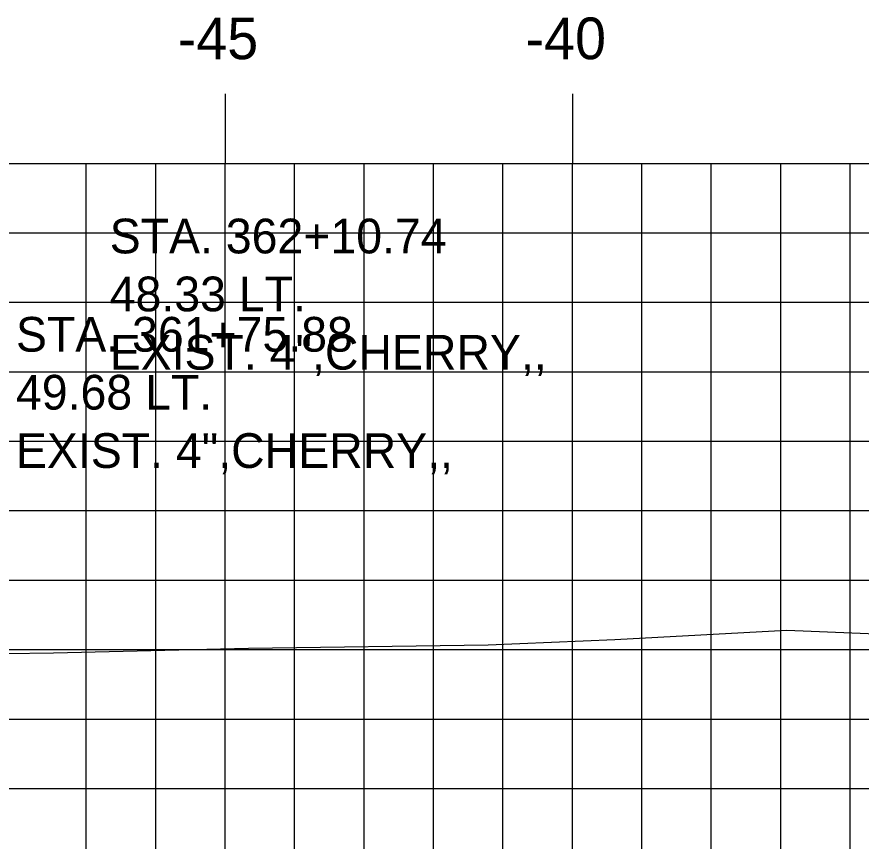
# Model space of a CAD drawing. Extents: x 1146746 to 1146916, y 608981 to 609091.
# Drawn here: x 1146781.43 to 1146793.59, y 609030.58 to 609042.44 of the extents above; entities that cross this region are included whole.
import ezdxf

# ---------------------------------------------------------------- set-up
doc = ezdxf.new("R2010")
doc.units = 0
for name, color, linetype in [('D_Text_Monospaced', 7, 'Continuous'), ('H_V ANNOTATION', 7, 'Continuous'), ('MAJOR', 7, 'Continuous'), ('MINOR', 7, 'Continuous'), ('S_Roadway_Centerline', 7, 'Continuous')]:
    doc.layers.add(name, color=color, linetype=linetype)

msp = doc.modelspace()

# ---------------------------------------------------------------- linework, layer by layer
at = {"layer": 'MAJOR'}
for p, q in [((1146784.428, 609041.337), (1146784.428, 609040.335)), ((1146789.428, 609041.337), (1146789.428, 609040.335)), ((1146759.428, 609040.335), (1146899.428, 609040.335)), ((1146759.428, 609040.335), (1146899.428, 609040.335)), ((1146784.428, 609020.335), (1146784.428, 609040.335)), ((1146789.428, 609020.335), (1146789.428, 609040.335)), ((1146759.428, 609035.335), (1146899.428, 609035.335))]:
    msp.add_line(p, q, dxfattribs=at)
at = {"layer": 'MINOR'}
for p, q in [((1146782.428, 609020.335), (1146782.428, 609040.335)), ((1146783.428, 609020.335), (1146783.428, 609040.335)), ((1146785.428, 609020.335), (1146785.428, 609040.335)), ((1146786.428, 609020.335), (1146786.428, 609040.335)), ((1146787.428, 609020.335), (1146787.428, 609040.335)), ((1146788.428, 609020.335), (1146788.428, 609040.335)), ((1146790.428, 609020.335), (1146790.428, 609040.335)), ((1146791.428, 609020.335), (1146791.428, 609040.335)), ((1146792.428, 609020.335), (1146792.428, 609040.335)), ((1146793.428, 609020.335), (1146793.428, 609040.335)), ((1146759.428, 609039.335), (1146899.428, 609039.335)), ((1146759.428, 609038.335), (1146899.428, 609038.335)), ((1146759.428, 609037.335), (1146899.428, 609037.335)), ((1146759.428, 609036.335), (1146899.428, 609036.335)), ((1146759.428, 609034.335), (1146899.428, 609034.335)), ((1146759.428, 609033.335), (1146899.428, 609033.335)), ((1146759.428, 609032.335), (1146899.428, 609032.335)), ((1146759.428, 609031.335), (1146899.428, 609031.335))]:
    msp.add_line(p, q, dxfattribs=at)
at = {"layer": 'S_Roadway_Centerline'}
msp.add_lwpolyline([(1146759.428, 609033.556), (1146762.881, 609033.501), (1146764.381, 609033.447), (1146765.249, 609033.421), (1146766.824, 609033.384), (1146767.963, 609033.367), (1146768.745, 609033.359), (1146770.475, 609033.354), (1146778.994, 609033.253), (1146779.894, 609033.259), (1146781.955, 609033.29), (1146784.763, 609033.357), (1146788.214, 609033.405), (1146790.04, 609033.481), (1146792.515, 609033.614), (1146794.858, 609033.519)], dxfattribs=at)

# ---------------------------------------------------------------- texts
at = {"layer": 'D_Text_Monospaced'}
for s, height, p in [('STA. 362+10.74', 0.49998, (1146782.766, 609039.039)), ('48.33 LT.', 0.5, (1146782.766, 609038.205)), ('STA. 361+75.88', 0.49998, (1146781.416, 609037.624)), ('EXIST. 4",CHERRY,,', 0.49998, (1146782.766, 609037.365)), ('49.68 LT.', 0.5, (1146781.416, 609036.79)), ('EXIST. 4",CHERRY,,', 0.49998, (1146781.416, 609035.95))]:
    msp.add_text(s, height=height, dxfattribs=at).set_placement(p)
at = {"layer": 'H_V ANNOTATION'}
for s, p in [('-45', (1146783.745, 609041.835)), ('-40', (1146788.753, 609041.835))]:
    msp.add_text(s, height=0.6, dxfattribs=at).set_placement(p)

doc.saveas('drawing.dxf')
